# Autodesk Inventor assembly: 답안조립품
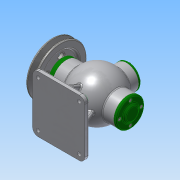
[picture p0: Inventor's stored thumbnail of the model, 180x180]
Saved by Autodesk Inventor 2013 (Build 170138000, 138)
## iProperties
Created: 2018-06
Part Number: 답안조립품
Document SubType Name: Assembly
Designer: Administrator
Author: Administrator
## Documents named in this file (19)
- C:\Users\Administrator\Desktop\480612V1017\답안조립품.iam
- C:\Users\Administrator\Desktop\480612V1017\본체.ipt
- C:\Users\Administrator\Desktop\480612V1017\V-벨트풀리.ipt
- C:\Users\Administrator\Desktop\480612V1017\너트 M8.ipt
- C:\Users\Administrator\Desktop\480612V1017\뒤커버.ipt
- C:\Users\Administrator\Desktop\480612V1017\멈춤링 15x1.ipt
- C:\Users\Administrator\Desktop\480612V1017\멈춤링 35x1.6.ipt
- 멈춤링 35x1.6.ipt
- C:\Users\Administrator\Desktop\480612V1017\베어링 6202.ipt
- 베어링 6202.ipt
- C:\Users\Administrator\Desktop\480612V1017\볼트 M4x12.ipt
- C:\Users\Administrator\Desktop\480612V1017\볼트 M4x16.ipt
- C:\Users\Administrator\Desktop\480612V1017\부시.ipt
- C:\Users\Administrator\Desktop\480612V1017\상부커버.ipt
- C:\Users\Administrator\Desktop\480612V1017\슬라이드.ipt
- C:\Users\Administrator\Desktop\480612V1017\앞커버.ipt
- C:\Users\Administrator\Desktop\480612V1017\오일 실 15 30 7.ipt
- C:\Users\Administrator\Desktop\480612V1017\키 4x4x12.ipt
- C:\Users\Administrator\Desktop\480612V1017\편심축.ipt
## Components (1 placed, 1 different names)
1. V-벨트풀리:1
